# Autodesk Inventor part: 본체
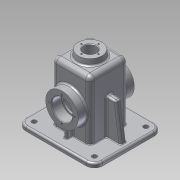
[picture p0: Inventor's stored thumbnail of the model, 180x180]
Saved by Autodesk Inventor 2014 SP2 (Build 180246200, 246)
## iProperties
Created: 2016-08
Part Number: 본체
Material: 알루미늄 6061
Document SubType Name: Modeling
Designer: user
Density: 2.71 g/cm^3
Appearance: 알루미늄 - 평지
Author: user
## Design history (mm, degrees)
sketch "스케치1"
  geometry: L1 (-65, -57.5)-(65, -57.5); L2 (65, -57.5)-(65, 57.5); L3 (65, 57.5)-(-65, 57.5); L4 (-65, 57.5)-(-65, -57.5); L5 (-65, -57.5)-(65, 57.5); L6 (65, -57.5)-(-65, 57.5); 1 further point
  constraints: 12 end point, 2 midpoint, 2 parallel, 1 horizontal, 1 perpendicular
  dimensions: "d0" = 130 distance of L3.end L2.end; "d1" = 115 distance of L2.end L1.end
extrude "돌출1" new body sketch "스케치1" distance "d2" = 10; taper "d3" = 0 deg
sketch "스케치2"
  geometry: L1 (-32.5, 32.5)-(32.5, 32.5); L2 (32.5, 32.5)-(32.5, -32.5); L3 (32.5, -32.5)-(-32.5, -32.5); L4 (-32.5, -32.5)-(-32.5, 32.5); L5 (-32.5, 32.5)-(32.5, -32.5); L6 (32.5, 32.5)-(-32.5, -32.5); 1 further point
  constraints: 12 end point, 2 midpoint, 2 parallel, 1 horizontal, 1 perpendicular
  dimensions: "d4" = 65 distance of L2.end L3.end; "d5" = 65 distance of L1.end L2.end
extrude "돌출2" join sketch "스케치2" distance "d6" = 100; taper "d7" = 0 deg
fillet "모깎기1" dims "d11" = 8
fillet "모깎기2" dims "d12" = 8
feature "쉘1" dims "d8" = 5
sketch "스케치4"
  geometry: L1 (32.5, 77)-(32.5, 28) reference; L2 (84.5, 80)-(35.5, 80) reference; L3 (87.5, 28)-(87.5, 77) reference; L4 (35.5, 25)-(84.5, 25) reference; L5 (120, 0)-(0, 0) reference; L6 (120, 105)-(120, 0) reference; L7 (0, 105)-(120, 105) reference; L8 (0, 0)-(0, 105) reference; A1 r 3 centre (35.5, 77) between (35.5, 80) and (32.5, 77) reference; A2 r 3 centre (84.5, 77) between (87.5, 77) and (84.5, 80) reference; A3 r 3 centre (84.5, 28) between (84.5, 25) and (87.5, 28) reference; A4 r 3 centre (35.5, 28) between (32.5, 28) and (35.5, 25) reference; 1 further point
extrude "돌출3" join sketch "스케치4" distance "d9" = 5; taper "d10" = 0 deg
node "작업 평면1"
sketch "스케치6"
  geometry: 1 further point
sketch "스케치7"
  geometry: C1 r 20 at (0, 0); 1 further point
  constraints: 1 centre point, 1 coincident
  dimensions: "d14" = 40 diameter of C1
extrude "돌출4" join sketch "스케치7" stored distance "d15" = 5; taper "d16" = 0 deg
feature "면 기울기1" dims angle "d17" = 7 deg
node "작업 평면2"
sketch "스케치8"
  geometry: L1 (-65, 0)-(65, 0) reference; C1 r 27.5 at (0, 55); 2 further points
  constraints: 1 centre point, 1 midpoint, 1 vertical alignment
  dimensions: "d19" = 55 diameter of C1; "d20" = 55 distance from line of L1 C1.centre
extrude "돌출5" join sketch "스케치8" stored distance "d21" = 15; taper "d22" = 0 deg
sketch "스케치9"
  geometry: L1 (47.5, 27.5)-(32.5, 27.5) reference; L2 (27.5, 102)-(27.5, 0) reference; L3 (32.5, 10)-(32.5, 42.51) reference; L4 (-57.5, 10)-(57.5, 10) reference; L5 (42.5, 27.5)-(42.5, 10); 1 further point
  constraints: 2 end point, 2 point on line, 1 perpendicular
  dimensions: "d23" = 15 distance between parallel lines of L2 L5
feature "리브1" sketch "스케치9" dims "d24" = 1, "d25" = 6, "d26" = 0, "d27" = 0, "d28" = 1, "d29" = 1
sketch "스케치10"
  geometry: L1 (-32.5, 10)-(-32.5, 102) reference; L2 (65, 10)-(-65, 10) reference; L3 (-57, 10)-(-48.568, 70); L4 (-48.568, 70)-(-32.5, 70); L5 (-65, 0)-(-65, 10) reference; L6 (65, 0)-(-65, 0) reference; 1 further point
  constraints: 4 end point, 2 point on line, 1 parallel
  dimensions: "d30" = 8 deg angle of L5 L3; "d31" = 8 distance of L3.start L2.end; "d32" = 70 distance between parallel lines of L6 L4
extrude "돌출6" join sketch "스케치10" stored distance "d33" = 10; taper "d34" = 0 deg
sketch "스케치11"
  geometry: C1 r 27.5 at (0, 0) reference; C2 r 15 at (0, 0); 1 further point
  constraints: 1 centre point, 1 coincident
  dimensions: "d35" = 30 diameter of C2
extrude "돌출7" cut sketch "스케치11" stored distance "d36" = 10; taper "d37" = 0 deg
sketch "스케치12"
  geometry: C1 r 15 at (0, 0) reference; C2 r 17.5 at (0, 0); 1 further point
  constraints: 1 centre point, 1 coincident
  dimensions: "d38" = 35 diameter of C2
extrude "돌출8" cut sketch "스케치12" distance "d39" = 17; taper "d40" = 0 deg
sketch "스케치13"
  geometry: C1 r 27.5 at (0, 0) reference; 2 further points
  constraints: 1 vertical alignment
  dimensions: "d41" = 21 distance of C1.centre point (0, -21)
hole "구멍1" sketch "스케치13" at (0, -21) diameter "d42" = 3.242; stored, may be unused: countersink angle "d46" = 90 deg, drill point angle "d48" = 118 deg; dims "d43" = 8, "d44" = 4, "d45" = 2, "d47" = 10
sketch "스케치14"
  geometry: C1 r 10.5 at (0, 0); 1 further point
  constraints: 1 centre point, 1 coincident
  dimensions: "d52" = 21 diameter of C1
extrude "돌출9" cut sketch "스케치14" stored distance "d53" = 17; taper "d54" = 0 deg
sketch "스케치15"
  geometry: C1 r 10.5 at (0, 0) reference; 2 further points
  constraints: 1 vertical alignment
  dimensions: "d55" = 14.5 distance of point (0, 0) point (0, -14.5)
hole "구멍2" sketch "스케치15" at (0, -14.5) diameter "d56" = 2.459; stored, may be unused: countersink angle "d60" = 90 deg, drill point angle "d62" = 118 deg; dims "d57" = 7, "d58" = 4, "d59" = 2, "d61" = 9
chamfer "모따기1" distance "d66" = 1; stored, may be unused: second distance "d67" = 2, angle "d68" = 45 deg
fillet "모깎기3" dims "d69" = 0.3
fillet "모깎기4" dims "d70" = 14
fillet "모깎기5" dims "d71" = 3
sketch "스케치16"
  geometry: L1 (-51, 57.5)-(51, 57.5) reference; L2 (-65, -43.5)-(-65, 43.5) reference; L3 (51, -57.5)-(-51, -57.5) reference; L4 (65, 43.5)-(65, -43.5) reference; L5 (-24.5, 27.5)-(24.5, 27.5) reference; L6 (27.5, 24.5)-(27.5, -24.5) reference; L7 (24.5, -27.5)-(-24.5, -27.5) reference; L8 (-27.5, -24.5)-(-27.5, 24.5) reference; L9 (60, 43.5)-(60, -43.5); L10 (51, -52.5)-(-51, -52.5); L11 (-60, -43.5)-(-60, 43.5); L12 (-51, 52.5)-(51, 52.5); A1 r 14 centre (51, 43.5) between (65, 43.5) and (51, 57.5) reference; A2 r 14 centre (-51, 43.5) between (-51, 57.5) and (-65, 43.5) reference; A3 r 14 centre (-51, -43.5) between (-65, -43.5) and (-51, -57.5) reference; A4 r 14 centre (51, -43.5) between (51, -57.5) and (65, -43.5) reference; A5 r 3 centre (24.5, 24.5) between (27.5, 24.5) and (24.5, 27.5) reference; A6 r 3 centre (24.5, -24.5) between (24.5, -27.5) and (27.5, -24.5) reference; A7 r 3 centre (-24.5, -24.5) between (-27.5, -24.5) and (-24.5, -27.5) reference; A8 r 3 centre (-24.5, 24.5) between (-24.5, 27.5) and (-27.5, 24.5) reference; A9 r 9 centre (51, 43.5) between (60, 43.5) and (51, 52.5); A10 r 9 centre (51, -43.5) between (51, -52.5) and (60, -43.5); A11 r 9 centre (-51, -43.5) between (-60, -43.5) and (-51, -52.5); A12 r 9 centre (-51, 43.5) between (-51, 52.5) and (-60, 43.5); 1 further point
  constraints: 8 end point, 8 point on circle, 4 centre point, 7 other
  dimensions: "d72" = 5 distance between parallel lines of L1 L12
extrude "돌출10" cut sketch "스케치16" distance "d73" = 3; taper "d74" = 0 deg
sketch "스케치17"
  geometry: C1 r 4 at (-51, -43.5); C2 r 4 at (51, -43.5); C3 r 4 at (51, 43.5); C4 r 4 at (-51, 43.5); A1 r 14 centre (-51, -43.5) between (-65, -43.5) and (-51, -57.5) reference; A2 r 14 centre (51, -43.5) between (51, -57.5) and (65, -43.5) reference; A3 r 14 centre (51, 43.5) between (65, 43.5) and (51, 57.5) reference; A4 r 14 centre (-51, 43.5) between (-51, 57.5) and (-65, 43.5) reference; 1 further point
  constraints: 4 centre point, 4 coincident
  dimensions: "d75" = 8 diameter of C1; "d78" = 8 diameter of C2; "d79" = 8 diameter of C3; "d80" = 8 diameter of C4
extrude "돌출12" cut sketch "스케치17" stored distance "d81" = 3; taper "d82" = 0 deg
sketch "스케치18"
  geometry: L1 (57, 0)-(57, 92) reference; L2 (44.5, -18)-(4.5, -18) reference; 2 further points
  constraints: 1 other
  dimensions: "d83" = 32.5 distance from line of L1 point (24.5, 8); "d84" = 26 distance from line of L2 point (24.5, 8)
feature "엠보싱1" sketch "스케치18" dims "d85" = 0.5, "d86" = 0
fillet "모깎기6" dims "d87" = 3
fillet "모깎기7" dims "d88" = 3
fillet "모깎기8" dims "d89" = 3
fillet "모깎기9" dims "d90" = 3
fillet "모깎기10" dims "d91" = 3
fillet "모깎기11" dims "d92" = 3
fillet "모깎기12" dims "d93" = 3
fillet "모깎기13" dims "d94" = 3
fillet "모깎기14" dims "d95" = 3
fillet "모깎기15" dims "d96" = 3
fillet "모깎기16" dims "d97" = 3
fillet "모깎기17" dims "d98" = 3
fillet "모깎기18" dims "d99" = 1
node "솔리드1"
mirror "대칭1"
mirror "대칭2"
mirror "대칭3"
mirror "대칭4"
pattern_circular "원형 패턴1" dims angle "d50" = 360 deg
mirror "대칭5"
pattern_circular "원형 패턴2" dims angle "d64" = 360 deg
node "투영된 루프1"
node "투영된 루프2"
other parameters: "d18" = 47.5
